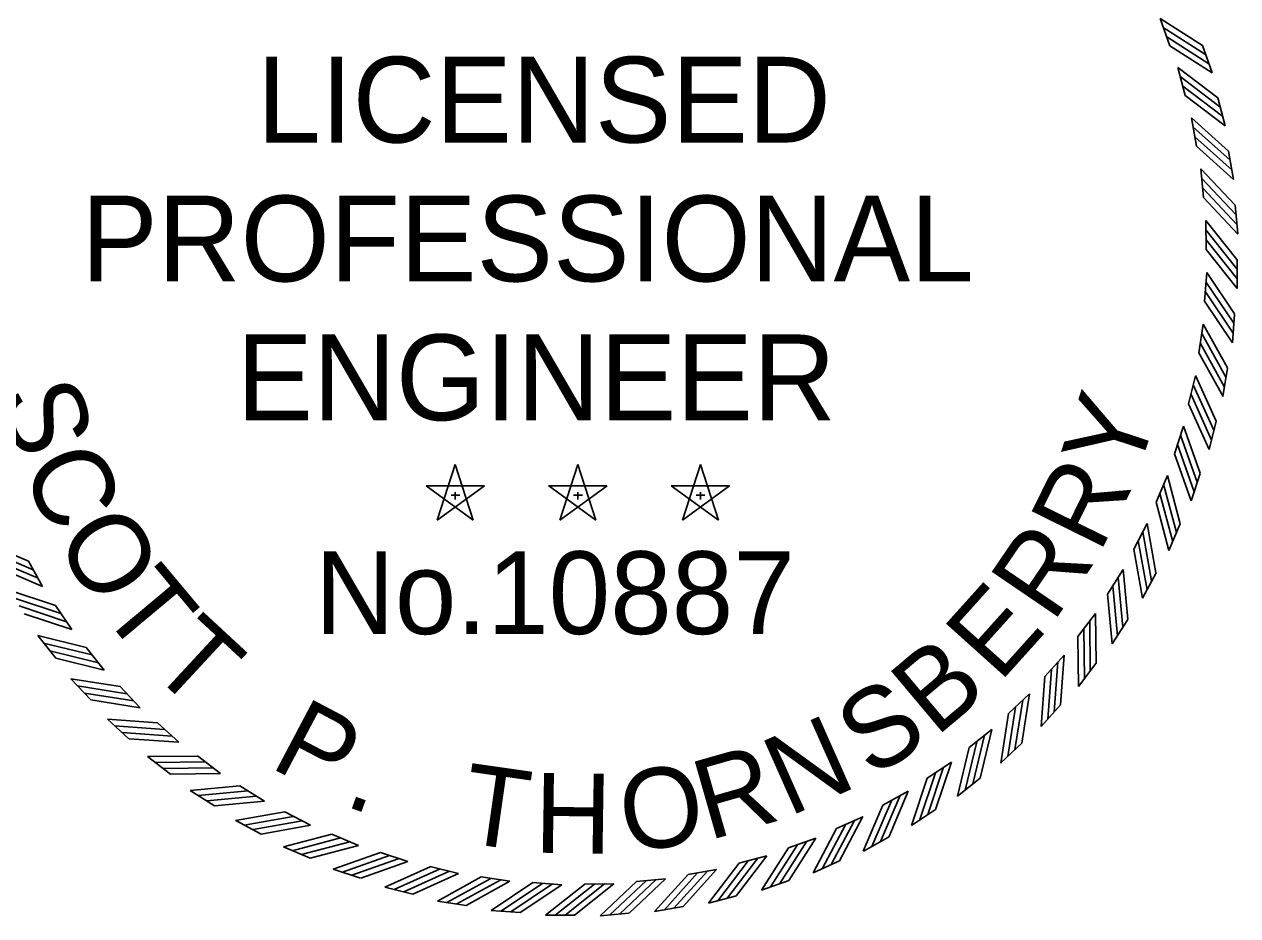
# Model space of a CAD drawing. Extents: x 1955708 to 1956002, y 566396 to 566594.
# Drawn here: x 1955978.59 to 1956000.59, y 566562.4 to 566578.57 of the extents above; entities that cross this region are included whole.
import ezdxf

# ---------------------------------------------------------------- set-up
doc = ezdxf.new("R2010")
doc.units = 0
doc.layers.add('STAMP_PP', color=7, linetype='Continuous')

msp = doc.modelspace()

# ---------------------------------------------------------------- linework, layer by layer
at = {"layer": 'STAMP_PP'}
for p, q in [((1955999.183, 566578.674), (1955999.358, 566578.178)), ((1955999.947, 566578.185), (1956000.122, 566577.691)), ((1955999.503, 566577.787), (1955999.637, 566577.279)), ((1956000.224, 566577.237), (1956000.358, 566576.73)), ((1955999.749, 566576.877), (1955999.84, 566576.36)), ((1956000.422, 566576.269), (1956000.513, 566575.753)), ((1955999.918, 566575.95), (1955999.967, 566575.427)), ((1956000.539, 566575.289), (1956000.587, 566574.767)), ((1956000.011, 566575.011), (1956000.016, 566574.486)), ((1956000.575, 566574.302), (1956000.58, 566573.778)), ((1956000.025, 566574.069), (1955999.987, 566573.545)), ((1956000.529, 566573.315), (1956000.491, 566572.792)), ((1955999.962, 566573.128), (1955999.881, 566572.609)), ((1955999.822, 566572.196), (1955999.697, 566571.686)), ((1956000.402, 566572.335), (1956000.32, 566571.818)), ((1956000.194, 566571.37), (1956000.07, 566570.86)), ((1955999.605, 566571.279), (1955999.439, 566570.781)), ((1955986.4, 566570.582), (1955986.072, 566569.576)), ((1955986.727, 566569.577), (1955986.401, 566570.583)), ((1955988.623, 566570.582), (1955988.295, 566569.576)), ((1955988.949, 566569.577), (1955988.623, 566570.583)), ((1955990.845, 566570.582), (1955990.518, 566569.576)), ((1955991.172, 566569.577), (1955990.846, 566570.583)), ((1955999.908, 566570.424), (1955999.742, 566569.927)), ((1955986.928, 566570.198), (1955985.871, 566570.199)), ((1955985.871, 566570.198), (1955986.727, 566569.575)), ((1955986.073, 566569.577), (1955986.93, 566570.198)), ((1955989.151, 566570.198), (1955988.093, 566570.199)), ((1955988.094, 566570.198), (1955988.949, 566569.575)), ((1955988.296, 566569.577), (1955989.152, 566570.198)), ((1955991.374, 566570.198), (1955990.316, 566570.199)), ((1955990.317, 566570.198), (1955991.172, 566569.575)), ((1955990.519, 566569.577), (1955991.375, 566570.198)), ((1955999.312, 566570.383), (1955999.106, 566569.9)), ((1955986.325, 566570.029), (1955986.482, 566570.029)), ((1955986.401, 566570.086), (1955986.401, 566569.953)), ((1955988.547, 566570.029), (1955988.705, 566570.029)), ((1955988.624, 566570.086), (1955988.624, 566569.953)), ((1955990.77, 566570.029), (1955990.927, 566570.029)), ((1955990.846, 566570.086), (1955990.846, 566569.953)), ((1955998.947, 566569.514), (1955998.701, 566569.049)), ((1955999.544, 566569.506), (1955999.338, 566569.024)), ((1955978.918, 566568.372), (1955978.664, 566568.832)), ((1955998.512, 566568.678), (1955998.228, 566568.235)), ((1955999.106, 566568.621), (1955998.86, 566568.158)), ((1955979.446, 566567.591), (1955979.154, 566568.028)), ((1955998.008, 566567.881), (1955997.69, 566567.463)), ((1955998.596, 566567.775), (1955998.313, 566567.333)), ((1955979.155, 566567.07), (1955978.829, 566567.481)), ((1955980.036, 566566.856), (1955979.71, 566567.268)), ((1955997.441, 566567.128), (1955997.089, 566566.738)), ((1955998.017, 566566.974), (1955997.699, 566566.557)), ((1955979.79, 566566.313), (1955979.431, 566566.695)), ((1955980.685, 566566.173), (1955980.326, 566566.556)), ((1955996.813, 566566.424), (1955996.43, 566566.065)), ((1955997.375, 566566.223), (1955997.024, 566565.834)), ((1955980.484, 566565.611), (1955980.096, 566565.962)), ((1955981.389, 566565.545), (1955980.999, 566565.897)), ((1955996.13, 566565.775), (1955995.718, 566565.449)), ((1955996.673, 566565.528), (1955996.291, 566565.17)), ((1955981.235, 566564.969), (1955980.818, 566565.287)), ((1955982.142, 566564.978), (1955981.724, 566565.297)), ((1955995.395, 566565.185), (1955994.958, 566564.893)), ((1955982.939, 566564.475), (1955982.496, 566564.758)), ((1955995.916, 566564.894), (1955995.506, 566564.568)), ((1955982.036, 566564.391), (1955981.595, 566564.673)), ((1955994.614, 566564.657), (1955994.154, 566564.402)), ((1955983.775, 566564.039), (1955983.311, 566564.285)), ((1955995.109, 566564.324), (1955994.673, 566564.033)), ((1955982.882, 566563.881), (1955982.419, 566564.126)), ((1955993.792, 566564.195), (1955993.313, 566563.98)), ((1955984.644, 566563.674), (1955984.161, 566563.88)), ((1955994.258, 566563.823), (1955993.8, 566563.569)), ((1955983.767, 566563.442), (1955983.285, 566563.648)), ((1955992.935, 566563.803), (1955992.44, 566563.628)), ((1955985.54, 566563.382), (1955985.042, 566563.548)), ((1955992.048, 566563.483), (1955991.54, 566563.35)), ((1955993.369, 566563.393), (1955992.891, 566563.178)), ((1955984.685, 566563.079), (1955984.188, 566563.244)), ((1955986.457, 566563.165), (1955985.947, 566563.289)), ((1955991.138, 566563.238), (1955990.621, 566563.146)), ((1955987.39, 566563.024), (1955986.871, 566563.106)), ((1955988.33, 566562.961), (1955987.806, 566562.999)), ((1955989.273, 566562.975), (1955988.747, 566562.971)), ((1955990.211, 566563.068), (1955989.688, 566563.02)), ((1955992.447, 566563.039), (1955991.953, 566562.864)), ((1955985.631, 566562.792), (1955985.122, 566562.916)), ((1955991.498, 566562.762), (1955990.992, 566562.629)), ((1955986.596, 566562.584), (1955986.079, 566562.666)), ((1955990.531, 566562.564), (1955990.015, 566562.473)), ((1955987.576, 566562.457), (1955987.053, 566562.496)), ((1955988.563, 566562.411), (1955988.039, 566562.406)), ((1955989.55, 566562.447), (1955989.028, 566562.399))]:
    msp.add_line(p, q, dxfattribs=at)
for points in [[(1955999.182, 566578.674), (1955999.947, 566578.186)], [(1955999.237, 566578.515), (1956000.001, 566578.026)], [(1955999.302, 566578.344), (1956000.066, 566577.856)], [(1955999.358, 566578.179), (1956000.122, 566577.691)], [(1955999.502, 566577.787), (1956000.224, 566577.238)], [(1955999.544, 566577.624), (1956000.265, 566577.074)], [(1955999.594, 566577.449), (1956000.315, 566576.899)], [(1955999.637, 566577.28), (1956000.358, 566576.73)], [(1955999.748, 566576.877), (1956000.421, 566576.27)], [(1955999.776, 566576.711), (1956000.449, 566576.104)], [(1955999.811, 566576.532), (1956000.485, 566575.925)], [(1955999.84, 566576.36), (1956000.513, 566575.753)], [(1955999.918, 566575.95), (1956000.539, 566575.289)], [(1955999.932, 566575.782), (1956000.553, 566575.121)], [(1955999.952, 566575.601), (1956000.573, 566574.94)], [(1955999.967, 566575.427), (1956000.588, 566574.766)], [(1956000.01, 566575.012), (1956000.574, 566574.302)], [(1956000.01, 566574.843), (1956000.574, 566574.134)], [(1956000.016, 566574.661), (1956000.58, 566573.952)], [(1956000.016, 566574.487), (1956000.58, 566573.777)], [(1956000.025, 566574.07), (1956000.529, 566573.316)], [(1956000.002, 566573.72), (1956000.505, 566572.966)], [(1956000.011, 566573.901), (1956000.515, 566573.147)], [(1955999.987, 566573.546), (1956000.491, 566572.792)], [(1955999.962, 566573.129), (1956000.402, 566572.336)], [(1955999.934, 566572.963), (1956000.374, 566572.17)], [(1955999.91, 566572.782), (1956000.349, 566571.989)], [(1955999.881, 566572.61), (1956000.321, 566571.817)], [(1955999.821, 566572.197), (1956000.194, 566571.37)], [(1955999.78, 566572.033), (1956000.153, 566571.207)], [(1955999.741, 566571.856), (1956000.113, 566571.029)], [(1955999.698, 566571.686), (1956000.071, 566570.86)], [(1955999.549, 566571.12), (1955999.853, 566570.266)], [(1955999.604, 566571.28), (1955999.907, 566570.425)], [(1955999.496, 566570.946), (1955999.799, 566570.092)], [(1955999.439, 566570.781), (1955999.742, 566569.926)], [(1955999.244, 566570.229), (1955999.476, 566569.352)], [(1955999.312, 566570.383), (1955999.544, 566569.507)], [(1955999.177, 566570.06), (1955999.408, 566569.183)], [(1955999.106, 566569.9), (1955999.338, 566569.023)], [(1955998.867, 566569.366), (1955999.025, 566568.473)], [(1955998.947, 566569.514), (1955999.105, 566568.622)], [(1955978.664, 566568.831), (1955977.83, 566569.187)], [(1955998.785, 566569.203), (1955998.944, 566568.31)], [(1955978.747, 566568.677), (1955977.913, 566569.033)], [(1955998.702, 566569.05), (1955998.86, 566568.157)], [(1955978.838, 566568.52), (1955978.004, 566568.876)], [(1955978.919, 566568.372), (1955978.085, 566568.728)], [(1955998.511, 566568.678), (1955998.596, 566567.776)], [(1955998.419, 566568.537), (1955998.503, 566567.634)], [(1955979.154, 566568.027), (1955978.294, 566568.313)], [(1955998.229, 566568.236), (1955998.313, 566567.333)], [(1955998.324, 566568.382), (1955998.409, 566567.479)], [(1955979.25, 566567.881), (1955978.389, 566568.167)], [(1955979.354, 566567.732), (1955978.494, 566568.018)], [(1955979.446, 566567.591), (1955978.586, 566567.876)], [(1955998.008, 566567.881), (1955998.018, 566566.975)], [(1955997.797, 566567.601), (1955997.807, 566566.694)], [(1955997.905, 566567.748), (1955997.914, 566566.842)], [(1955979.71, 566567.267), (1955978.829, 566567.481)], [(1955979.817, 566567.129), (1955978.936, 566567.343)], [(1955997.69, 566567.463), (1955997.699, 566566.557)], [(1955979.933, 566566.989), (1955979.052, 566567.203)], [(1955997.441, 566567.128), (1955997.375, 566566.224)], [(1955980.037, 566566.856), (1955979.156, 566567.07)], [(1955997.327, 566567.004), (1955997.261, 566566.1)], [(1955980.326, 566566.555), (1955979.431, 566566.695)], [(1955997.09, 566566.738), (1955997.024, 566565.834)], [(1955997.208, 566566.867), (1955997.142, 566565.962)], [(1955980.445, 566566.427), (1955979.549, 566566.567)], [(1955980.572, 566566.297), (1955979.676, 566566.437)], [(1955980.686, 566566.173), (1955979.79, 566566.313)], [(1955996.689, 566566.311), (1955996.549, 566565.415)], [(1955996.814, 566566.425), (1955996.673, 566565.529)], [(1955996.431, 566566.065), (1955996.291, 566565.169)], [(1955996.559, 566566.183), (1955996.419, 566565.288)], [(1955980.999, 566565.897), (1955980.095, 566565.962)], [(1955981.128, 566565.778), (1955980.223, 566565.844)], [(1955981.266, 566565.659), (1955980.361, 566565.725)], [(1955981.39, 566565.545), (1955980.485, 566565.611)], [(1955995.997, 566565.672), (1955995.783, 566564.791)], [(1955996.13, 566565.776), (1955995.916, 566564.895)], [(1955995.719, 566565.449), (1955995.506, 566564.568)], [(1955995.857, 566565.556), (1955995.643, 566564.675)], [(1955981.725, 566565.296), (1955980.818, 566565.287)], [(1955981.862, 566565.189), (1955980.956, 566565.18)], [(1955995.395, 566565.185), (1955995.11, 566564.325)], [(1955982.009, 566565.081), (1955981.103, 566565.072)], [(1955982.142, 566564.978), (1955981.236, 566564.969)], [(1955995.105, 566564.989), (1955994.819, 566564.128)], [(1955995.254, 566565.093), (1955994.969, 566564.233)], [(1955982.497, 566564.757), (1955981.594, 566564.673)], [(1955994.959, 566564.893), (1955994.673, 566564.033)], [(1955982.643, 566564.662), (1955981.74, 566564.578)], [(1955982.798, 566564.567), (1955981.896, 566564.483)], [(1955994.309, 566564.486), (1955993.953, 566563.652)], [(1955994.466, 566564.577), (1955994.11, 566563.743)], [(1955994.614, 566564.657), (1955994.259, 566563.823)], [(1955982.94, 566564.475), (1955982.037, 566564.391)], [(1955983.311, 566564.284), (1955982.418, 566564.126)], [(1955994.155, 566564.402), (1955993.799, 566563.568)], [(1955983.464, 566564.201), (1955982.572, 566564.043)], [(1955983.627, 566564.119), (1955982.734, 566563.961)], [(1955983.776, 566564.039), (1955982.883, 566563.881)], [(1955993.474, 566564.05), (1955993.05, 566563.248)], [(1955993.638, 566564.128), (1955993.215, 566563.326)], [(1955993.793, 566564.196), (1955993.369, 566563.394)], [(1955984.161, 566563.88), (1955983.285, 566563.648)], [(1955993.314, 566563.98), (1955992.89, 566563.178)], [(1955984.321, 566563.81), (1955983.445, 566563.578)], [(1955984.49, 566563.742), (1955983.613, 566563.51)], [(1955984.645, 566563.674), (1955983.768, 566563.442)], [(1955992.44, 566563.628), (1955991.952, 566562.864)], [(1955992.605, 566563.685), (1955992.117, 566562.92)], [(1955992.776, 566563.749), (1955992.288, 566562.985)], [(1955992.935, 566563.804), (1955992.447, 566563.04)], [(1955985.042, 566563.547), (1955984.188, 566563.244)], [(1955985.207, 566563.49), (1955984.353, 566563.187)], [(1955985.381, 566563.437), (1955984.527, 566563.134)], [(1955985.541, 566563.382), (1955984.686, 566563.079)], [(1955991.71, 566563.392), (1955991.161, 566562.671)], [(1955991.885, 566563.442), (1955991.336, 566562.721)], [(1955992.049, 566563.484), (1955991.499, 566562.763)], [(1955985.948, 566563.288), (1955985.121, 566562.916)], [(1955986.117, 566563.245), (1955985.29, 566562.873)], [(1955986.295, 566563.206), (1955985.468, 566562.834)], [(1955986.458, 566563.165), (1955985.632, 566562.792)], [(1955990.794, 566563.175), (1955990.186, 566562.501)], [(1955990.972, 566563.21), (1955990.365, 566562.537)], [(1955991.139, 566563.238), (1955990.531, 566562.565)], [(1955991.541, 566563.349), (1955990.991, 566562.628)], [(1955986.871, 566563.105), (1955986.078, 566562.665)], [(1955987.043, 566563.076), (1955986.25, 566562.637)], [(1955987.224, 566563.052), (1955986.431, 566562.612)], [(1955987.39, 566563.024), (1955986.597, 566562.585)], [(1955987.807, 566562.999), (1955987.053, 566562.495)], [(1955987.981, 566562.984), (1955987.227, 566562.481)], [(1955988.163, 566562.975), (1955987.409, 566562.471)], [(1955988.331, 566562.961), (1955987.577, 566562.458)], [(1955988.748, 566562.97), (1955988.038, 566562.406)], [(1955988.923, 566562.97), (1955988.213, 566562.406)], [(1955989.105, 566562.976), (1955988.395, 566562.412)], [(1955989.273, 566562.976), (1955988.563, 566562.412)], [(1955989.688, 566563.019), (1955989.028, 566562.399)], [(1955989.862, 566563.034), (1955989.202, 566562.413)], [(1955990.043, 566563.054), (1955989.382, 566562.434)], [(1955990.211, 566563.068), (1955989.551, 566562.448)], [(1955990.621, 566563.146), (1955990.014, 566562.473)]]:
    msp.add_lwpolyline(points, dxfattribs=at)

# ---------------------------------------------------------------- texts
for s, height, p in [('LICENSED', 1.5559, (1955982.804, 566576.426)), ('PROFESSIONAL', 1.55591, (1955979.618, 566573.907)), ('ENGINEER', 1.5559, (1955982.433, 566571.388)), ('No.10887', 1.5003, (1955983.856, 566567.509))]:
    msp.add_text(s, height=height, dxfattribs=at).set_placement(p)
for s, rotation, p in [('S', 286.9475, (1955978.115, 566571.864)), ('Y', 71.7733, (1955998.744, 566570.319)), ('C', 294.2435, (1955978.518, 566570.543)), ('R', 63.7477, (1955998.081, 566568.953)), ('O', 301.9044, (1955979.117, 566569.223)), ('R', 55.7221, (1955997.234, 566567.692)), ('T', 309.93, (1955979.928, 566567.939)), ('E', 48.0613, (1955996.269, 566566.611)), ('T', 317.226, (1955980.814, 566566.88)), ('B', 40.0357, (1955995.112, 566565.626)), ('S', 32.7397, (1955993.951, 566564.88)), ('P', 332.1828, (1955983.011, 566565.105)), ('N', 23.9845, (1955992.446, 566564.187)), ('R', 15.9589, (1955990.989, 566563.76)), ('T', 351.882, (1955986.463, 566563.738)), ('H', 359.178, (1955987.83, 566563.543)), ('O', 7.9332, (1955989.486, 566563.541)), ('.', 340.2084, (1955984.359, 566564.405))]:
    msp.add_text(s, height=1.448, rotation=rotation, dxfattribs=at).set_placement(p)

doc.saveas('drawing.dxf')
